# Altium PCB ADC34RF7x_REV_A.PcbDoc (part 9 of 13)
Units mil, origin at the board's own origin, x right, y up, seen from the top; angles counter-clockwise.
Board outline 6250 x 2716.54 mil, 18 copper layers (Top Layer, L2 GND, L3 PWR, L4 GND, L5 PWR/SIG, L6 GND, L7 SIGNAL, L8 GND, L9 GND, L10 SIGNAL, L11 GND, L12 SIGNAL, L13 GND, L14 PWR, L15 GND, L16 PWR/SIG, L16 GND, Bottom Layer), stack 95.314 mil thick; 668 components, 786 nets, 3150 pads, 2020 vias.
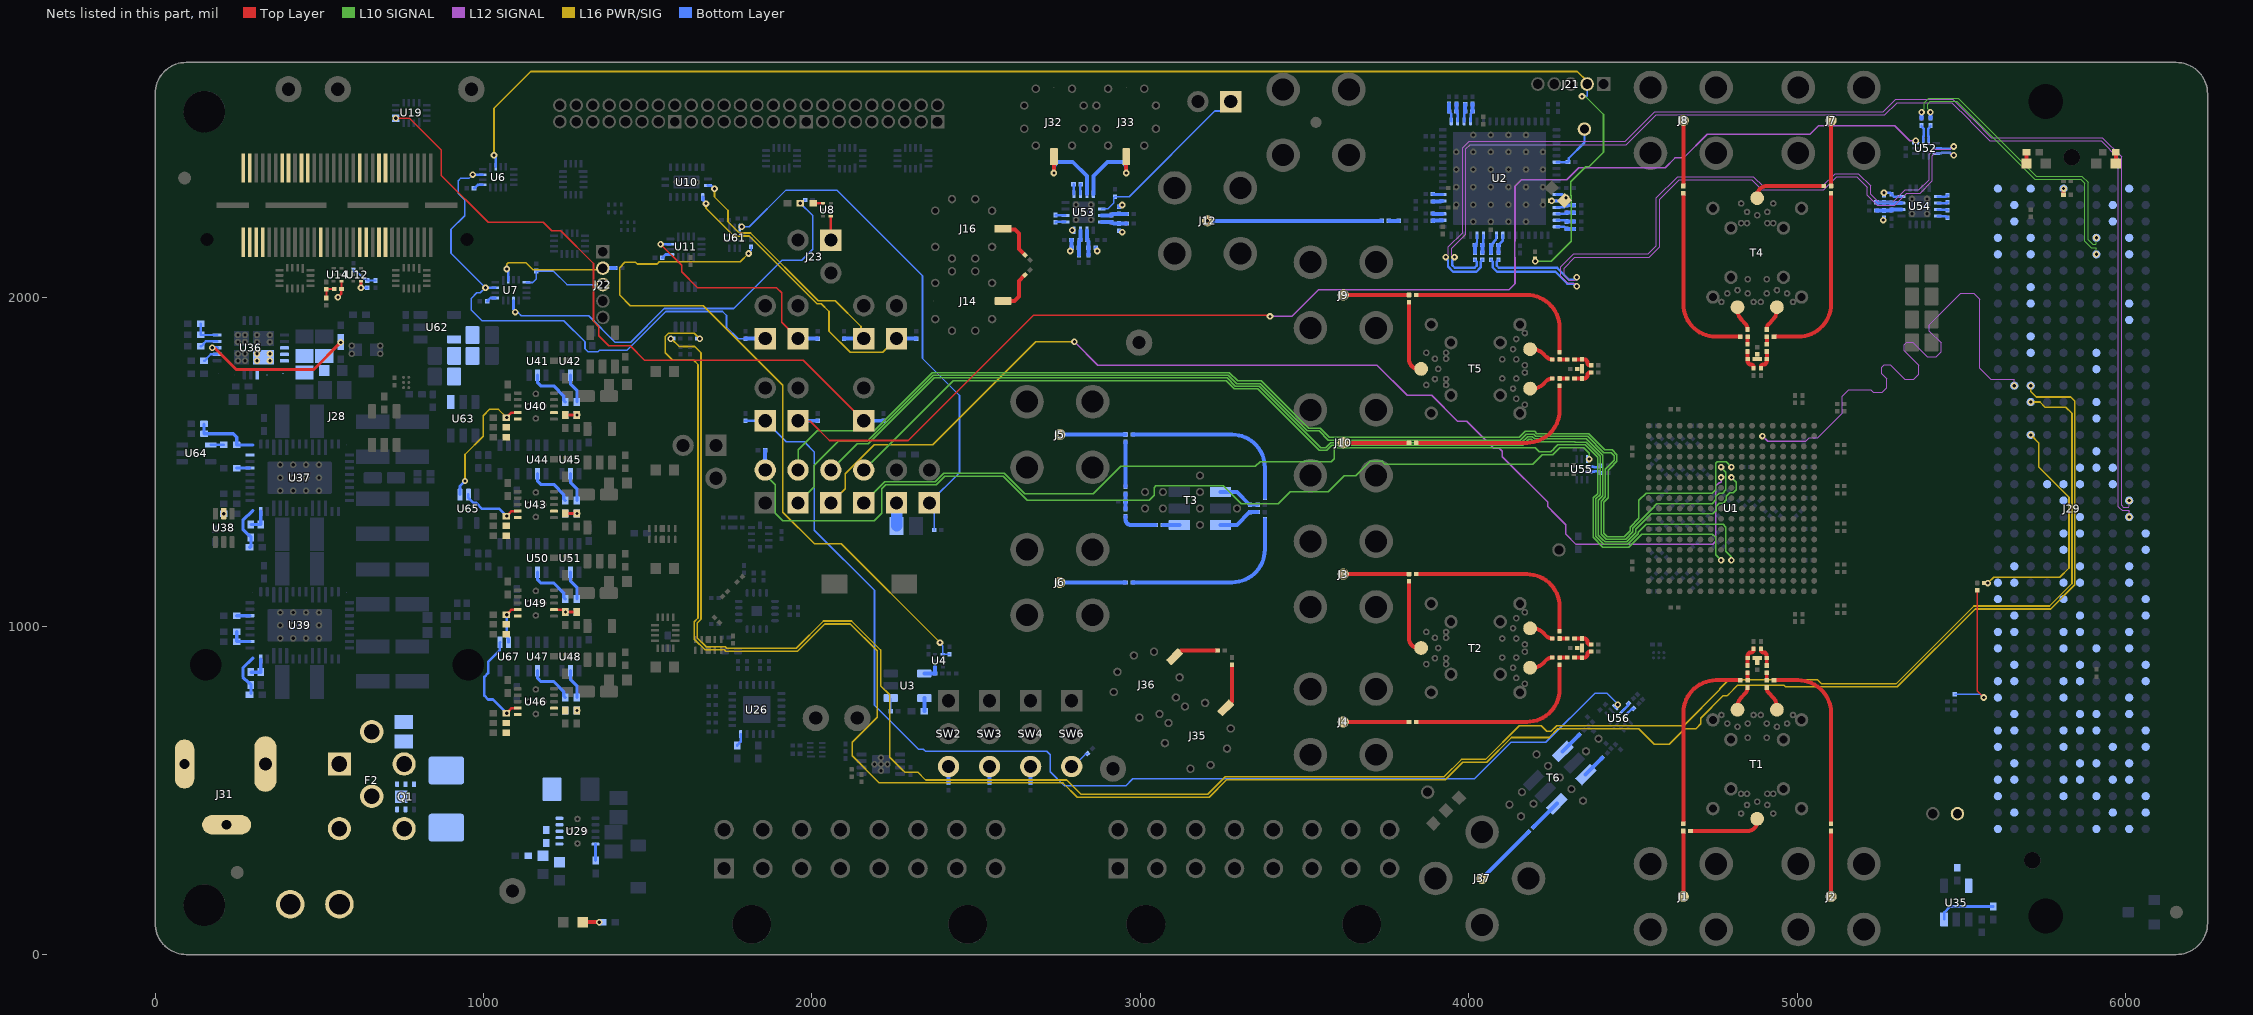
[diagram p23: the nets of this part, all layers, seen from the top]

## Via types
v1: diameter 20, hole 10, Top Layer to Bottom Layer, tented both sides, 1793 vias
v2: diameter 24, hole 12, Top Layer to Bottom Layer, tented both sides, 168 vias
v3: diameter 18, hole 8, Top Layer to Bottom Layer, tented both sides, 59 vias

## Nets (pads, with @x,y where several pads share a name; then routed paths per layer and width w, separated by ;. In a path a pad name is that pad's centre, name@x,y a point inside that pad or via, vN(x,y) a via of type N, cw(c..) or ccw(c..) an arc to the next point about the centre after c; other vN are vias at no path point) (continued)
LVDSB15_P: J29.J13 U1.F2 | length 1593.7
  L12 SIGNAL w3.5: 5025.69,1562.24 5037.18,1573.74 5063.44,1573.74 5122.33,1632.63 5137.41,1647.71 5137.41,1700.68 5156.58,1719.85 5223.68,1719.85 5231.29,1712.24 5258.63,1712.24 5272.65,1726.26 5272.65,1753.6 5257.04,1769.21 5257.04,1788.27 5265.21,1796.44 5284.27,1796.44 5328.44,1752.26 5355.78,1752.26 5369.8,1766.29 5369.8,1793.63 5325.63,1837.8 5325.63,1856.86 5333.8,1865.03 5352.85,1865.03 5397.03,1820.85 5424.37,1820.85 5438.39,1834.88 5438.39,1862.22 5402.22,1898.39 5402.22,1917.45 5497.93,2013.16 5537.24,2013.16 5555.61,1994.8 5555.61,1785.94 5572.01,1769.53 5589.27,1752.27 5659.37,1752.27 5661.42,1750.22 v1(5661.42,1732.27)
  L12 SIGNAL w4: v1(4894.49,1578.74) 4910.98,1562.24 5025.69,1562.24
MGTREFCLK0_FMC_N: C64.1 J29.D5 | length 876.9
  L10 SIGNAL w3.5: v1@5399.59,2564.64 v1(5406.04,2564.64) 5406.04,2566.3 5397.54,2574.8 5397.54,2589.76 5405.56,2597.78 5486.61,2597.78 5644.81,2439.58 5723.8,2360.59 5863.42,2360.59 5876,2348.02 5876,2338.55 5876.17,2338.38 5876.17,2226.16 5876,2225.99 5876,2188.55 5876.17,2188.38 5876.17,2171.96 5895.86,2152.27 5909.37,2152.27 5911.42,2150.22 v1(5911.42,2132.27)
  Bottom Layer w12.1: v1(5406.04,2564.64) 5406.04,2546.68 C64.1@5406.15,2546.56
MGTREFCLK0_FMC_P: C59.1 J29.D4 | length 893.7
  L10 SIGNAL w3.5: v1@5385.48,2564.64 v1(5379.03,2564.64) 5379.03,2566.3 5387.54,2574.8 5387.54,2593.9 5401.42,2607.78 5490.76,2607.78 5654.81,2443.73 5727.94,2370.59 5867.57,2370.59 5886,2352.16 5886,2342.69 5886.17,2342.52 5886.17,2222.02 5886,2221.85 5886,2192.69 5886.17,2192.52 5886.17,2176.1 5900,2162.27 5909.37,2162.27 5911.42,2164.32 v1(5911.42,2182.27)
  Bottom Layer w12.1: C59.1@5378.8,2546.45 5378.92,2546.56 5378.92,2564.52 v1(5379.03,2564.64)
MGTREFCLK0_LMK_N: R63.2 U52.4 | length 2044.3
  L12 SIGNAL w3.5: v1(4328.98,2035.16) 4328.98,2041.61 4326.93,2043.66 4301.69,2043.66 4280.33,2065.02 4280.33,2094.54 4319.56,2133.77 4546.13,2133.77 4571.14,2158.78 4571.14,2303.99 4636.27,2369.12 4866.61,2369.12 4896.62,2339.11 5077.11,2339.11 5115.93,2377.93 5186.41,2377.93 5223.58,2340.76 5223.58,2315.56 5247.62,2291.53 5293.42,2291.53 5330.09,2328.2 5370.61,2328.2 5402.2,2359.78 5402.2,2436.2 5418.02,2452.01 5466.47,2452.01 5474.97,2460.51 v1(5476.64,2460.51)
  Bottom Layer w7.4: R63.2@4068.18,2115.38 4068.18,2114.6 4073.3,2109.47 4073.3,2092.06 4086.29,2079.07 4263.96,2079.07 4300.57,2042.46 4318.35,2042.46 4325.65,2035.16 v1(4328.98,2035.16) ; U52.4@5424.03,2454.89 5424.27,2454.65 5438.81,2454.65 5440.25,2453.21 5466,2453.21 5473.3,2460.51 v1(5476.64,2460.51)
MGTREFCLK0_LMK_P: R62.2 U52.5 | length 1990.6
  L12 SIGNAL w3.5: v1(4328.98,2062.16) 4328.98,2055.71 4326.93,2053.66 4305.83,2053.66 4290.33,2069.16 4290.33,2090.4 4323.71,2123.77 4550.28,2123.77 4581.14,2154.64 4581.14,2299.85 4640.41,2359.12 4862.47,2359.12 4889.54,2332.04 4892.47,2329.11 5081.26,2329.11 5120.07,2367.93 5182.27,2367.93 5213.58,2336.62 5213.58,2311.42 5243.47,2281.53 5297.57,2281.53 5334.23,2318.2 5374.76,2318.2 5412.2,2355.64 5412.2,2432.05 5422.16,2442.01 5466.47,2442.01 5474.97,2433.51 v1(5476.64,2433.51)
  Bottom Layer w7.4: R62.2@4090.83,2115.38 4090.83,2114.6 4085.7,2109.47 4085.7,2097.2 4091.42,2091.47 4269.09,2091.47 4305.71,2054.86 4318.35,2054.86 4325.65,2062.16 v1(4328.98,2062.16) ; U52.5@5424.03,2439.14 5424.27,2439.38 5438.81,2439.38 5440.25,2440.81 5466,2440.81 5473.3,2433.51 v1(5476.64,2433.51)
MGTREFCLK1_FMC_N: C67.2 J29.B21 | length 3715.4
  L12 SIGNAL w3.5: v1(3956.79,2123.77) 3950.34,2123.77 3948.29,2125.82 3948.29,2150.43 3991.79,2193.93 3991.79,2452.89 4005.1,2466.2 4480.35,2466.2 4537.66,2523.52 4556.41,2542.27 4571.14,2557 5266.89,2557 5304.26,2594.36 5470.59,2594.36 5522.21,2542.75 5531.82,2533.14 5587.23,2477.73 5925.71,2477.73 5978,2425.43 5978,1363.9 5980.93,1360.97 5989.63,1352.27 6009.37,1352.27 6011.42,1350.22 v1(6011.42,1332.27)
  Bottom Layer w7.4: v1(3956.79,2123.77) 3956.79,2120.44 3949.49,2113.14 3949.49,2099.7 3957.71,2091.47 4018.21,2091.47 4023.93,2097.2 4023.93,2109.47 4018.81,2114.6 C67.2@4018.81,2115.38
MGTREFCLK1_FMC_P: C66.2 J29.B20 | length 3773.1
  L12 SIGNAL w3.5: v1(3929.79,2123.77) 3936.24,2123.77 3938.29,2125.82 3938.29,2154.57 3981.79,2198.07 3981.79,2457.03 4000.96,2476.2 4476.2,2476.2 4533.52,2533.52 4552.27,2552.27 4567,2567 5262.75,2567 5300.12,2604.36 5474.73,2604.36 5526.35,2552.75 5538.89,2540.21 5591.37,2487.73 5929.85,2487.73 5988,2429.57 5988,1368.04 5993.77,1362.27 6009.37,1362.27 6011.42,1364.32 v1(6011.42,1382.27)
  Bottom Layer w7.4: v1(3929.79,2123.77) 3929.79,2120.44 3937.09,2113.14 3937.09,2094.56 3952.57,2079.07 4023.35,2079.07 4036.33,2092.06 4036.33,2109.47 4041.46,2114.6 C66.2@4041.46,2115.38
NetC1_1: C1.1 C2.1 | length 567.7
  Top Layer w12.1: C2.1@4653.52,398.38 4653.52,735.2 cw(c4753.52,735.2) 4753.52,835.2 C1.1@4827.35,835.2
NetC1_2: C1.2 C3.2 R1.1 | length 23
  Top Layer w12.1: C1.2@4849.4,835.2 R1.1@4849.4,858.2
NetC2_2: C2.2 C4.1 J1.1 | length 200
  Top Layer w12.1: J1.1@4653.52,176.33 C2.2@4653.52,376.33
NetC3_1: C3.1 T1.2 | length 77.5
  Top Layer w12.1: T1.2@4818.52,745.38 4818.52,753 cw(c4862.74,753) 4831.47,784.27 4841.64,794.44 ccw(c4822.93,813.16) C3.1@4849.4,813.16
NetC4_2: C4.2 T1.1 | length 227.6
  Top Layer w12.1: C4.2@4675.57,376.33 4849.52,376.33 ccw(c4849.52,405.33) 4878.52,405.33 T1.1@4878.52,413.38
NetC5_2: C5.2 R3.1 R5.2
NetC6_1: C6.1 T1.3 | length 77.5
  Top Layer w12.1: C6.1@4907.64,813.16 ccw(c4934.11,813.16) 4915.4,794.44 4925.57,784.27 cw(c4894.3,753) 4938.52,753 T1.3@4938.52,745.38
NetC6_2: C6.2 C7.1 R6.1 | length 23
  Top Layer w12.1: C6.2@4907.64,835.2 R6.1@4907.64,858.2
NetC7_2: C7.2 C8.2 | length 567.7
  Top Layer w12.1: C7.2@4929.69,835.2 5003.52,835.2 cw(c5003.52,735.2) 5103.52,735.2 C8.2@5103.52,398.38
NetC8_1: C8.1 J2.1 | length 200
  Top Layer w12.1: J2.1@5103.52,176.33 C8.1@5103.52,376.33
NetC9_1: C9.1 C10.1 | length 567.7
  Top Layer w12.1: C10.1@3840.11,1158.29 4176.94,1158.29 cw(c4176.94,1058.29) 4276.94,1058.29 C9.1@4276.94,984.46
NetC9_2: C9.2 C11.2 R8.1 | length 23
  Top Layer w12.1: C9.2@4276.94,962.41 R8.1@4299.94,962.41
NetC10_2: C10.2 C12.1 J3.1 | length 200
  Top Layer w12.1: J3.1@3618.06,1158.29 C10.2@3818.06,1158.29
NetC11_1: C11.1 T2.2 | length 77.5
  Top Layer w12.1: T2.2@4187.11,993.29 4194.73,993.29 cw(c4194.73,949.07) 4226,980.34 4236.17,970.17 ccw(c4254.89,988.88) C11.1@4254.89,962.41
NetC12_2: C12.2 T2.1 | length 227.6
  Top Layer w12.1: C12.2@3818.06,1136.24 3818.06,962.29 ccw(c3847.06,962.29) 3847.06,933.29 T2.1@3855.11,933.29
NetC13_2: C13.2 R10.1 R12.2
NetC14_1: C14.1 T2.3 | length 77.5
  Top Layer w12.1: T2.3@4187.11,873.29 4194.73,873.29 ccw(c4194.73,917.51) 4226,886.24 4236.17,896.42 cw(c4254.89,877.7) C14.1@4254.89,904.17
NetC14_2: C14.2 C15.1 R13.1 | length 23
  Top Layer w12.1: C14.2@4276.94,904.17 R13.1@4299.94,904.17
NetC15_2: C15.2 C16.2 | length 567.7
  Top Layer w12.1: C16.2@3840.11,708.29 4176.94,708.29 ccw(c4176.94,808.29) 4276.94,808.29 C15.2@4276.94,882.12
NetC16_1: C16.1 J4.1 | length 200
  Top Layer w12.1: J4.1@3618.06,708.29 C16.1@3818.06,708.29
NetC17_1: C17.1 C18.1 | length 550.9
  Bottom Layer w12.1: C17.1@2977.05,1583.28 3279.28,1583.28 cw(c3279.28,1483.28) 3379.28,1483.28 C18.1@3379.28,1391.65
NetC17_2: C17.2 C20.1 J5.1 | length 200
  Bottom Layer w12.1: v1(2755,1583.28) C17.2@2955,1583.28
NetC19_1: C19.1 R17.1 T3.6 | length 129
  Bottom Layer w12.1: T3.6@3244.24,1408.28 3294.24,1408.28 3332.91,1369.6 C19.1@3357.24,1369.6
NetC20_2: C20.2 R15.1 | length 136.8
  Bottom Layer w12.1: R15.1@2955,1424.47 C20.2@2955,1561.23
NetC21_1: C21.1 R16.2 | length 111.2
  Bottom Layer w12.1: R16.2@2955,1334.38 2955,1324.38 ccw(c2971.1,1324.38) 2971.1,1308.28 C21.1@3046.99,1308.28
NetC21_2: C21.2 T3.3 | length 50
  Bottom Layer w12.1: C21.2@3069.04,1308.28 T3.3@3119.04,1308.28
NetC22_1: C22.1 R17.2 T3.4 | length 129
  Bottom Layer w12.1: T3.4@3244.24,1308.28 3294.24,1308.28 3332.91,1346.96 C22.1@3357.24,1346.96
NetC23_2: C23.2 C24.2 | length 550.9
  Bottom Layer w12.1: C24.2@2977.05,1133.28 3279.28,1133.28 ccw(c3279.28,1233.28) 3379.28,1233.28 C23.2@3379.28,1324.91
NetC24_1: C24.1 J6.1 | length 200
  Bottom Layer w12.1: v1(2755,1133.28) C24.1@2955,1133.28
NetC25_1: C25.1 C27.1 | length 567.7
  Top Layer w12.1: C25.1@4929.71,1881.33 5003.54,1881.33 ccw(c5003.54,1981.33) 5103.54,1981.33 C27.1@5103.54,2318.16
NetC25_2: C25.2 C26.2 R19.1 | length 23
  Top Layer w12.1: R19.1@4907.67,1858.33 C25.2@4907.67,1881.33
NetC26_1: C26.1 T4.2 | length 77.5
  Top Layer w12.1: C26.1@4907.67,1903.38 cw(c4934.14,1903.38) 4915.42,1922.1 4925.59,1932.27 ccw(c4894.32,1963.54) 4938.54,1963.54 T4.2@4938.54,1971.16
NetC27_2: C27.2 C28.1 J7.1 | length 200
  Top Layer w12.1: C27.2@5103.54,2340.21 J7.1@5103.54,2540.21
NetC28_2: C28.2 T4.1 | length 227.6
  Top Layer w12.1: T4.1@4878.54,2303.16 4878.54,2311.21 cw(c4907.54,2311.21) 4907.54,2340.21 C28.2@5081.5,2340.21
NetC29_2: C29.2 R21.1 R23.2
NetC30_1: C30.1 T4.3 | length 77.5
  Top Layer w12.1: T4.3@4818.54,1971.16 4818.54,1963.54 ccw(c4862.76,1963.54) 4831.5,1932.27 4841.67,1922.1 cw(c4822.95,1903.38) C30.1@4849.42,1903.38
NetC30_2: C30.2 C31.1 R24.1 | length 23
  Top Layer w12.1: R24.1@4849.42,1858.33 C30.2@4849.42,1881.33
NetC31_2: C31.2 C32.2 | length 567.7
  Top Layer w12.1: C32.2@4653.54,2318.16 4653.54,1981.33 ccw(c4753.54,1981.33) 4753.54,1881.33 C31.2@4827.38,1881.33
NetC32_1: C32.1 J8.1 | length 200
  Top Layer w12.1: C32.1@4653.54,2340.21 J8.1@4653.54,2540.21
NetC33_1: C33.1 C34.1 | length 567.7
  Top Layer w12.1: C34.1@3840.11,2008.27 4176.94,2008.27 cw(c4176.94,1908.27) 4276.94,1908.27 C33.1@4276.94,1834.44
NetC33_2: C33.2 C35.2 R26.1 | length 23
  Top Layer w12.1: C33.2@4276.94,1812.39 R26.1@4299.94,1812.39
NetC34_2: C34.2 C36.1 J9.1 | length 200
  Top Layer w12.1: J9.1@3618.06,2008.27 C34.2@3818.06,2008.27
NetC35_1: C35.1 T5.2 | length 77.5
  Top Layer w12.1: T5.2@4187.11,1843.27 4194.73,1843.27 cw(c4194.73,1799.05) 4226,1830.32 4236.17,1820.14 ccw(c4254.89,1838.86) C35.1@4254.89,1812.39
NetC36_2: C36.2 T5.1 | length 227.6
  Top Layer w12.1: C36.2@3818.06,1986.22 3818.06,1812.27 ccw(c3847.06,1812.27) 3847.06,1783.27 T5.1@3855.11,1783.27
NetC37_2: C37.2 R28.1 R30.2
NetC38_1: C38.1 T5.3 | length 77.5
  Top Layer w12.1: T5.3@4187.11,1723.27 4194.73,1723.27 ccw(c4194.73,1767.49) 4226,1736.22 4236.17,1746.39 cw(c4254.89,1727.68) C38.1@4254.89,1754.15
NetC38_2: C38.2 C39.1 R31.1 | length 23
  Top Layer w12.1: C38.2@4276.94,1754.15 R31.1@4299.94,1754.15
NetC39_2: C39.2 C40.2 | length 567.7
  Top Layer w12.1: C40.2@3840.11,1558.27 4176.94,1558.27 ccw(c4176.94,1658.27) 4276.94,1658.27 C39.2@4276.94,1732.1
NetC40_1: C40.1 J10.1 | length 200
  Top Layer w12.1: J10.1@3618.06,1558.27 C40.1@3818.06,1558.27
NetC53_1: C53.1 U2.37 | length 30.6
  Bottom Layer w12.1: C53.1@3890.96,2293.26 3914.83,2293.26 3916.33,2294.76 U2.37@3920.96,2294.76
NetC54_1: C54.1 U2.38 | length 30.6
  Bottom Layer w10: C54.1@3890.96,2315.95 3891.75,2315.95 3893.25,2314.45 U2.38@3920.96,2314.45
NetC56_1: C56.1 R33.2 | length 30
  Bottom Layer w12.1: C56.1@3756.86,2234.21 R33.2@3786.86,2234.21
NetC56_2: C56.2 J12.1 | length 530
  Bottom Layer w12.1: v1(3204.82,2234.21) C56.2@3734.82,2234.21
NetC57_2: C57.2 U2.35 | length 30.9
  Bottom Layer w12.1: C57.2@3890.96,2256.89 ccw(c3892.46,2256.89) 3892.46,2255.39 U2.35@3920.96,2255.39
NetC59_2: C59.2 U52.1 | length 51.8
  Bottom Layer w7.4: C59.2@5378.8,2524.4 5378.8,2521.06 5386.1,2513.76 5386.1,2492.52 5384.66,2491.09 U52.1@5384.66,2476.54 U52.1@5384.42,2476.31
NetC62_2: C62.2 R157.1 R158.1 R208.1 R209.1 U53.8 | length 72
  Bottom Layer w9: v1(2792.78,2205.32) U53.8@2797.78,2205.32 ; R158.1@2863.88,2152.32 2864.67,2152.32 2866.47,2150.52 2866.47,2149.73 2866.78,2149.42 2866.78,2144.42 v1(2868.88,2142.32)
  Bottom Layer w12: v1(2786.58,2142.37) 2786.58,2144.53 2790.29,2148.24 C62.2@2790.29,2175.32 ; R208.1@2935.43,2277.31 2935.43,2278.1 2935.73,2278.4 2939.35,2278.4 2943.27,2282.31 v1(2945.43,2282.31) ; R209.1@2939.51,2203.72 2943.21,2200.01 v1(2945.38,2200.01)
NetC63_2: C63.2 R159.1 R160.1 U54.8 | length 73.1
  Bottom Layer w8: v1@5264.71,2236.37 R160.1@5264.73,2243.46 ; R159.1@5264.73,2312.6 v1(5264.74,2319.69) 5283.09,2319.69 5284.64,2318.14 5285.43,2318.14 5287.73,2315.84 C63.2@5287.73,2315.05 5287.73,2314.26 5290.03,2311.97 5290.81,2311.97 5295.13,2307.65 U54.8@5317.73,2307.65
  other v1: 5262.71,2236.37
NetC64_2: C64.2 U52.2 | length 51.8
  Bottom Layer w7.4: U52.2@5400.53,2476.42 5400.29,2476.66 5400.29,2491.21 5398.85,2492.64 5398.85,2513.88 5406.15,2521.18 C64.2@5406.15,2524.52
NetC65_2: C65.2 U56.1 | length 32.3
  Bottom Layer w7.4: U56.1@4467.01,740.38 4486.14,759.51 4486.14,764.01 C65.2@4486.7,764.57
NetC66_1: C66.1 R37.1 U2.27 | length 55
  Bottom Layer w7.4: R37.1@4041.46,2160.18 4041.69,2160.18 4044.54,2163.03 4044.54,2166.93 4044.97,2167.37 U2.27@4044.97,2190.43
  Bottom Layer w12.1: R37.1@4041.16,2160.43 R37.1@4041.16,2160.43 4041.46,2160.18 C66.1@4041.46,2137.43
NetC67_1: C67.1 R37.2 U2.28 | length 56.6
  Bottom Layer w7.4: R37.2@4018.81,2160.18 4019.65,2160.18 4022.49,2163.03 4022.49,2164.57 4025.29,2167.37 U2.28@4025.29,2190.43
  Bottom Layer w12.1: C67.1@4018.81,2137.43 4018.81,2160.18 R37.2@4019.11,2160.43 R37.2@4019.11,2160.43
NetC68_2: C68.2 U56.2 | length 32.3
  Bottom Layer w7.4: U56.2@4478.15,729.24 4497.33,748.42 4501.73,748.42 C68.2@4502.29,748.98
NetC69_2: C69.2 U3.5 | length 40
  Bottom Layer w12: C69.2@2342.36,740.77 U3.5@2342.36,780.77
NetC70_1: C70.1 U2.34 | length 30.9
  Bottom Layer w12.1: C70.1@3890.96,2234.21 cw(c3892.46,2234.21) 3892.46,2235.71 U2.34@3920.96,2235.71
NetC71_1: C71.1 D4.2 F1.2 F2.2 Q1.3 R108.2 U29.3 U29.4 U29.5
NetC71_2: C71.2 D4.1 F2.4 Q1.1 Q1.2 Q1.5 Q1.6 Q1.8
NetC72_1: C72.1 U2.11 | length 40.3
  Bottom Layer w8: U2.11@4274.49,2314.45 U2.11@4267.42,2314.45 4281.49,2314.44 4285.82,2314.44 4295.82,2304.43 v1(4296.5,2304.43)
NetC73_1: C73.1 U2.12 | length 26
  Top Layer w8: C73.1@4248.78,2295.44 4249.44,2294.78 v1(4253.33,2294.78)
  Bottom Layer w8: v1(4253.33,2294.78) U2.12@4267.42,2294.76 ; U2.12@4260.34,2294.76 U2.12@4267.42,2294.76
NetC74_2: C74.2 PP1.1 U35.5
NetC75_2: C75.2 T6.6 | length 70.7
  Bottom Layer w12: T6.6@4286.29,618.57 C75.2@4336.29,668.57
NetC97_2: C97.2 R108.1 R111.2 U29.2
NetC98_2: C98.2 U29.1
NetC99_2: C99.2 T6.4 | length 70.7
  Bottom Layer w12: T6.4@4356.34,548.51 C99.2@4406.34,598.51
NetC100_1: C100.1 R188.1 R208.2 U53.3 | length 77.9
  Bottom Layer w12.1: U53.3@2882.43,2250.59 2911.25,2250.59 R188.1@2912.43,2251.77 2915.93,2255.27 R208.2@2935.43,2255.27 C100.1@2958.43,2255.27
NetC101_1: C101.1 R188.2 R209.2 U53.4 | length 77.7
  Bottom Layer w12.1: U53.4@2882.43,2230.9 2911.25,2230.9 2911.39,2230.76 2912.18,2230.76 2912.43,2230.51 R188.2@2912.43,2229.72 2919.77,2226.22 R209.2@2935.43,2226.22 C101.1@2958.43,2226.22
NetC108_1: C108.1 R132.2 R134.2 R136.2 U40.7 | length 35
  Top Layer w10: C108.1@1249.61,1643.03 v1(1284.61,1643.03)
NetC109_1: C109.1 R138.2 R140.2 R142.2 U43.7 | length 35
  Top Layer w10: C109.1@1249.61,1343.03 v1(1284.61,1343.03)
NetC122_1: C122.1 R144.1 R146.2 R148.2 U46.7
  other v1: 1284.61,743.03
NetC124_1: C124.1 R150.1 R152.2 R154.2 U49.7 | length 73.7
  Top Layer w8: U49.7@1214.61,1050.12 1243.76,1050.12 1249.61,1044.28 v1(1249.61,1043.03)
  Top Layer w10: v1(1249.61,1043.03) R152.2@1284.61,1043.03
NetC130_1: C130.1 C131.1 C167.1 FB1.1 U36.10 U36.11 U36.12 U36.13 U36.14 U36.15 U36.27
NetC184_2: C184.2 C187.2 C188.2 C189.2 U62.5 U63.1
NetC205_2: C205.2 U36.21 | length 49.4
  Bottom Layer w7: C205.2@149.09,1807.64 151.06,1807.64 157.4,1813.98 157.4,1815.95 169.09,1827.64 U36.21@189.09,1827.64
NetC218_2: C218.2 U37.44 | length 40
  Bottom Layer w9: C218.2@248.38,1481.3 U37.44@288.38,1481.3
NetC227_2: C227.2 U39.44 | length 40
  Bottom Layer w10: C227.2@248.38,1031.81 U39.44@288.38,1031.81
NetC259_1: C259.1 R158.2 R175.2 U53.6 | length 77.9
  Bottom Layer w12.1: U53.6@2837.16,2205.32 2837.16,2176.49 R175.2@2838.34,2175.32 2841.84,2171.82 R158.2@2841.84,2152.32 C259.1@2841.84,2129.32
NetC260_1: C260.1 R157.2 R175.1 U53.7 | length 77.7
  Bottom Layer w12.1: C260.1@2812.79,2129.32 R157.2@2812.79,2152.32 2812.79,2167.98 R175.1@2816.29,2175.32 2817.08,2175.32 2817.33,2175.57 2817.33,2176.35 2817.47,2176.49 U53.7@2817.47,2205.32
NetC261_1: C261.1 R160.2 R176.2 U54.6 | length 78
  Bottom Layer w12.1: C261.1@5241.73,2265.68 5281.4,2265.68 5281.86,2266.15 5287.48,2266.15 5287.73,2266.4 R176.2@5287.73,2267 5287.73,2267.97 5287.98,2268.22 5288.76,2268.22 5288.82,2268.27 U54.6@5317.73,2268.27
NetC262_1: C262.1 R159.2 R176.1 U54.7 | length 78
  Bottom Layer w12.1: C262.1@5241.73,2290.55 R159.2@5264.73,2290.55 5281.4,2290.55 5281.86,2290.09 5287.48,2290.09 5287.73,2289.84 R176.1@5287.73,2289.05 5287.73,2288.26 5287.98,2288.02 5288.76,2288.02 5288.82,2287.96 U54.7@5317.73,2287.96
NetC265_1: C265.1 T6.3 | length 100
  Bottom Layer w12.1: C265.1@4197.76,388.62 T6.3@4268.47,459.33
NetC265_2: C265.2 J37.1 | length 200
  Bottom Layer w12.1: v1(4040.75,231.61) C265.2@4182.17,373.03
NetD1_2: D1.2 R83.2 | length 35
  Top Layer w12: D1.2@5970.47,2408.52 R83.2@5970.47,2443.52
NetD2_2: D2.2 R87.2 | length 35
  Top Layer w12: D2.2@5698.36,2408.51 R87.2@5698.36,2443.51
NetD3_2: D3.2 R110.2 | length 50
  Top Layer w12: D3.2@1302.21,98.59 v1(1352.21,98.59)
NetF2_1: F2.1 J31.1 TP11.1
NetF2_3: F2.3 J31.2 J31.3 TP12.1
NetJ14_1: J14.1 R43.2 | length 127.2
  Top Layer w12.1: J14.1@2581.34,1989.11 J14.1@2582.11,1989.88 2582.88,1990.65 2617.49,1990.65 2630.09,2003.25 2630.09,2050.81 R43.2@2647.8,2068.52
NetJ15_1: J15.1 U1.K14 | length 3134.5
  L10 SIGNAL w4: J15.1@2157.76,1375.36 2221.38,1438.99 2374.87,1438.99 2401.38,1465.49 2586.06,1465.49 2648.86,1402.69 2856.38,1402.69 2941.18,1487.5 3350.8,1487.5 3364.56,1501.26 3499.58,1501.26 3500.06,1501.73 3540.51,1501.73 3541.4,1500.84 3581.85,1500.84 3590.63,1509.63 3590.63,1539.19 3593.83,1542.39 4203.21,1542.39 4215.32,1530.29 4250.53,1530.29 4259.32,1539.07 4259.32,1539.91 4271.15,1551.74 4354.17,1551.74 4392.31,1513.6 4392.31,1403.83 4379.07,1390.6 4379.07,1270.01 4408.31,1240.78 4487.51,1240.78 4524,1277.27 4524,1277.44 4526.34,1279.78 4742.22,1279.78 4752.01,1269.99 4752.01,1217.26 v1(4768.5,1200.76)
NetJ15_2: J15.2 U1.J14 | length 3274.4
  L10 SIGNAL w4: J15.2@2157.76,1475.36 2430.12,1747.73 3261.33,1747.73 3286.55,1722.52 3357.91,1722.52 3545.46,1534.96 3567.28,1534.96 3582.71,1550.39 4164.11,1550.39 4182.2,1568.49 4191.09,1568.49 4197.66,1561.92 4322.82,1561.92 4324.99,1559.74 4357.48,1559.74 4400.31,1516.92 4400.31,1400.52 4387.07,1387.28 4387.07,1273.5 4400.31,1260.27 4400.31,1260.09 4403.62,1256.78 4403.79,1256.78 4406.62,1253.96 4406.62,1253.78 4411.62,1248.78 4484.19,1248.78 4516,1280.59 4516,1286.07 4540.2,1310.28 4774.72,1310.28 4783.5,1301.49 4783.5,1227.57 4800,1211.07 v1(4800,1200.76)
NetJ16_1: J16.1 R44.2 | length 127.2
  Top Layer w12.1: J16.1@2582.11,2209.88 2583.65,2208.34 2618.26,2208.34 2630.86,2195.74 2630.86,2148.18 R44.2@2648.57,2130.47
NetJ17_1: J17.1 U1.K6 | length 3421.9
  L16 PWR/SIG w4: J17.1@2057.76,1375.36 2101.18,1418.79 2101.18,1463.86 2189.23,1551.91 2368.12,1551.91 2681.82,1865.61 v1(2799.42,1865.61)
  L12 SIGNAL w4: 4528.51,1248.78 4743.22,1248.78 4752.76,1258.31 4752.76,1426.72 4762.29,1436.26 4766.16,1436.26 4768.5,1438.6 v1(4768.5,1452.76)
  L12 SIGNAL w5: v1(2799.42,1865.61) 2870.76,1794.27 3720.9,1794.27 3812.48,1702.69 3887.18,1702.69 3966.06,1623.81 3994.18,1623.81 4076.26,1541.73 4093.04,1541.73 4102.12,1532.65 4102.12,1515.86 4240.28,1377.71 4240.28,1364.34 4263.72,1340.9 4263.72,1340.58 4295.16,1309.14 4295.16,1280.3 4326.68,1248.78 4528.51,1248.78
NetJ17_2: J17.2 U1.J6 | length 3398.2
  L10 SIGNAL w4: J17.2@2057.76,1475.36 2137.35,1554.95 2172.07,1554.95 2372.85,1755.73 3264.65,1755.73 3289.86,1730.52 3361.72,1730.52 3548.97,1543.27 3554.32,1543.27 3554.63,1542.96 3563.97,1542.96 3579.4,1558.39 4160.79,1558.39 4179.19,1576.78 4194.11,1576.78 4200.97,1569.92 4358.62,1569.92 4408.31,1520.23 4408.31,1397.2 4395.07,1383.97 4395.07,1276.81 4408.31,1263.58 4415.11,1256.78 4480.88,1256.78 4508,1283.9 4508,1295 4555.77,1342.77 4742.73,1342.77 4753.41,1353.46 4753.41,1364.39 4763.6,1374.58 4774.53,1374.58 4784.63,1384.67 4784.63,1395.6 4794.53,1405.51 4805.47,1405.51 4815,1415.05 4815,1437.76 v1(4800,1452.76)
NetJ18_1: J18.1 U1.K5 | length 3595.1
  L10 SIGNAL w4: J18.1@1957.76,1375.36 2006.83,1424.44 2006.83,1489.43 2080.35,1562.95 2168.76,1562.95 2369.54,1763.73 3267.96,1763.73 3293.17,1738.52 3365.03,1738.52 3508.92,1594.63 3544.17,1594.63 3572.4,1566.39 4157.31,1566.39 4175.7,1584.78 4197.42,1584.78 4204.29,1577.92 4361.93,1577.92 4411.4,1528.45 4434,1528.45 4443.37,1519.08 4443.37,1505.83 4433.78,1496.23 4433.78,1495.34 4416.43,1477.99 4416.43,1394.01 4403.07,1380.66 4403.07,1280.13 4418.42,1264.78 4477.57,1264.78 4500,1287.21 4500,1298.32 4564.53,1362.84 4564.53,1364.48 4573.31,1373.27 4741.73,1373.27 4752.76,1384.3 4752.76,1395.23 4762.29,1404.76 4773.22,1404.76 4783.5,1415.05 4783.5,1458.97 4783.46,1459.01 4783.46,1469.29 v1(4768.5,1484.25)
NetJ18_2: J18.2 U1.J5 | length 3605.9
  L10 SIGNAL w4: J18.2@1957.76,1475.36 1957.76,1536.42 2016.7,1595.36 2189.86,1595.36 2366.22,1771.73 3271.28,1771.73 3296.49,1746.52 3368.34,1746.52 3500.06,1614.8 3501.27,1614.8 3513.45,1602.63 3547.48,1602.63 3575.72,1574.39 4153.99,1574.39 4172.39,1592.78 4200.73,1592.78 4207.6,1585.92 4365.24,1585.92 4414.71,1536.45 4437.32,1536.45 4451.37,1522.39 4451.37,1502.51 4441.78,1492.92 4441.78,1492.03 4424.43,1474.68 4424.43,1390.7 4411.07,1377.34 4411.07,1283.44 4421.73,1272.78 4474.25,1272.78 4492,1290.53 4492,1301.63 4518.46,1328.09 4518.46,1383.02 4540.2,1404.76 4741.73,1404.76 4752.5,1415.54 4752.5,1495.34 4757.41,1500.25 4784,1500.25 v1(4800,1484.25)
NetJ19_1: J19.1 R51.1 | length 70
  Bottom Layer w35: R51.1@2257.76,1305.36 J19.1@2257.76,1375.36
NetJ21_2: J21.2 R53.2 U6.2 | length 4294
  Top Layer w8: R53.2@4202.45,2111.31 R53.2@4202.45,2118.38
  L16 PWR/SIG w5: v1(1031.86,2433.62) 1031.86,2576.86 1144.04,2689.04 4330.96,2689.04 4360.66,2659.34 J21.2@4360.66,2650.7
  L10 SIGNAL w5: v1(4202.44,2111.3) 4251.7,2111.3 4312,2171.59 4312,2310.85 4311.05,2311.81 4311.05,2353.05 4356.66,2398.66 4366.32,2398.66 4410.66,2443 4410.66,2557.88 4355.54,2613 v1(4345.07,2613)
  Bottom Layer w5: v1(4345.07,2613) 4361.07,2613 4361.07,2650.28 J21.2@4360.66,2650.7
  Bottom Layer w8: v1(1031.86,2433.62) 1031.86,2430.37 1036.86,2425.37 U6.2@1036.86,2398.62
NetJ22_2: J22.2 R59.1 U7.2 | length 393.4
  L16 PWR/SIG w5: v1(1070.49,2087.4) 1071.02,2087.94 1071.02,2101.62 1075.44,2106.04 1129.66,2106.04 1150.73,2084.97 1358.5,2084.97 J22.2@1363.54,2090.01
  Bottom Layer w8: v1(1070.49,2087.4) 1070.49,2084.15 1075.49,2079.15 U7.2@1075.49,2054.37 U7.2@1075.49,2052.4
  Bottom Layer w12: J22.2@1363.54,2090.01 R59.1@1400.32,2090.01
NetJ22_3: J22.3 R187.1 U7.5 | length 279.3
  Bottom Layer w5: U7.5@1130.6,2046.5 1149.91,2046.5 1156.02,2052.6 1156.02,2052.7 1159.82,2056.5 1160.6,2056.5 R187.1@1160.6,2081.5 1212.77,2081.5 1254.25,2040.01 J22.3@1363.54,2040.01
NetJ23_1: J23.1 U8.1 | length 73
  Top Layer w8: J23.1@2057.76,2175.36 U8.1@2057.76,2248.38
NetJ24_1: J24.1 R73.1 U6.15 U7.15 | length 1664.5
  Bottom Layer w5: v1(967.49,2375) 955.78,2363.28 929.87,2363.28 923,2356.41 923,2317.7 942.45,2298.25 942.45,2250.01 901,2208.57 901,2135.86 v1(1006.12,2030.75) 990.37,2015 979.82,2015 962.71,1997.89 962.71,1962.52 995.48,1929.75 1244.67,1929.75 1308.85,1865.57 1308.85,1844.65 1317.97,1835.53 1348.36,1835.53 1353.33,1840.5 1436.81,1840.5 1554.56,1958.25 1727.62,1958.25 1740.12,1945.74 1740.12,1910.94 1775.7,1875.36 R73.1@1797.76,1875.36
  Bottom Layer w8: v1(967.49,2375) U6.15@997.49,2375 ; v1(1006.12,2030.75) U7.15@1036.12,2030.75
  Bottom Layer w12: R73.1@1797.76,1875.36 J24.1@1857.76,1875.36
NetJ25_1: J25.1 R74.1 U11.15 | length 691.9
  Top Layer w5: v1(1539.13,2163.03) 1603.5,2098.66 1603.5,2078.64 1651.27,2030.88 1891.76,2030.88 1907.71,2014.92 1907.71,1925.41 J25.1@1957.76,1875.36
  Bottom Layer w8: v1(1539.13,2163.03) U11.15@1569.13,2163.03
  Bottom Layer w12: J25.1@1957.76,1875.36 R74.1@2017.76,1875.36
NetJ26_1: J26.1 R72.1 U10.9 | length 779.5
  L16 PWR/SIG w5: v1(1703.31,2332.09) 1703.31,2306.94 1744.46,2265.79 1744.46,2231.36 1778.79,2197.03 1813.21,2197.03 2019.38,1990.86 2070.95,1990.86 2149.4,1912.41 2149.4,1883.72 J26.1@2157.76,1875.36
  Bottom Layer w8: U10.9@1683.31,2342.09 1684.03,2341.36 1692.62,2341.36 1701.9,2332.09 v1(1703.31,2332.09)
  Bottom Layer w12: R72.1@2097.76,1875.36 J26.1@2157.76,1875.36
NetJ27_1: J27.1 R71.1 U10.10 | length 913.1
  L16 PWR/SIG w5: v1(1677.56,2286.65) 1677.56,2272.19 1761.72,2188.03 1809.49,2188.03 2015.65,1981.86 2028.38,1981.86 2052.14,1958.11 2052.14,1897.88 2116.46,1833.56 2215.95,1833.56 J27.1@2257.76,1875.36
  Bottom Layer w8: U10.10@1667.56,2306.65 1668.28,2305.93 1668.28,2297.34 1677.56,2288.06 v1(1677.56,2286.65)
  Bottom Layer w12: J27.1@2257.76,1875.36 R71.1@2317.76,1875.36
NetJ28_15: J28.15
NetJ28_16: J28.16
NetJ28_17: J28.17
NetJ28_18: J28.18
NetJ28_22: J28.22
NetJ28_23: J28.23
NetJ28_24: J28.24
NetJ28_36: J28.36
NetJ28_39: J28.39
NetJ28_41: J28.41
NetJ28_45: J28.45
NetJ28_47: J28.47
NetJ28_54: J28.54
NetJ28_56: J28.56
NetJ28_57: J28.57
NetJ28_58: J28.58
NetJ28_59: J28.59
NetJ28_60: J28.60
NetJ29_A22: J29.A22
NetJ29_A23: J29.A23
NetJ29_A26: J29.A26
NetJ29_A27: J29.A27
NetJ29_A30: J29.A30
NetJ29_A31: J29.A31
NetJ29_A34: J29.A34
NetJ29_A35: J29.A35
NetJ29_A38: J29.A38
NetJ29_A39: J29.A39
NetJ29_B1: J29.B1
NetJ29_B4: J29.B4
NetJ29_B5: J29.B5
NetJ29_B8: J29.B8
NetJ29_B9: J29.B9
NetJ29_B24: J29.B24
NetJ29_B25: J29.B25
NetJ29_B28: J29.B28
NetJ29_B29: J29.B29
NetJ29_B32: J29.B32
NetJ29_B33: J29.B33
NetJ29_B36: J29.B36
NetJ29_B37: J29.B37
NetJ29_B40: J29.B40
NetJ29_C2: J29.C2
NetJ29_C3: J29.C3
NetJ29_C18: J29.C18
NetJ29_C19: J29.C19
NetJ29_C35: J29.C35
NetJ29_C37: J29.C37
NetJ29_C39: J29.C39
NetJ29_D11: J29.D11
NetJ29_D12: J29.D12
NetJ29_D14: J29.D14
NetJ29_D15: J29.D15
NetJ29_D17: J29.D17
NetJ29_D18: J29.D18
NetJ29_D29: J29.D29
NetJ29_D33: J29.D33
NetJ29_D34: J29.D34
NetJ29_D36: J29.D36
NetJ29_D38: J29.D38
NetJ29_D40: J29.D40
NetJ29_E18: J29.E18
NetJ29_E19: J29.E19
NetJ29_E21: J29.E21
NetJ29_E22: J29.E22
NetJ29_E24: J29.E24
NetJ29_E25: J29.E25
NetJ29_E27: J29.E27
NetJ29_E28: J29.E28
NetJ29_E30: J29.E30
NetJ29_E31: J29.E31
NetJ29_E33: J29.E33
NetJ29_E34: J29.E34
NetJ29_E36: J29.E36
NetJ29_E37: J29.E37
NetJ29_F1: J29.F1 R85.2 | length 18.7
  Top Layer w12: R85.2@5811.42,2313.53 v1(5811.42,2332.27)
NetJ29_F19: J29.F19
NetJ29_F20: J29.F20
NetJ29_F22: J29.F22
NetJ29_F23: J29.F23
NetJ29_F25: J29.F25
NetJ29_F26: J29.F26
NetJ29_F28: J29.F28
NetJ29_F29: J29.F29
NetJ29_F31: J29.F31
NetJ29_F32: J29.F32
NetJ29_F34: J29.F34
NetJ29_F35: J29.F35
NetJ29_F37: J29.F37
NetJ29_F38: J29.F38
NetJ29_G19: J29.G19
NetJ29_H1: J29.H1
NetJ29_H4: J29.H4
NetJ29_H5: J29.H5
NetJ29_H7: J29.H7
NetJ29_H8: J29.H8
NetJ29_H10: J29.H10
NetJ29_H11: J29.H11
NetJ29_H13: J29.H13 R217.2 | length 6939.4
  L16 PWR/SIG w5: v1(1658.32,1875.36) 1641.82,1891.86 1563.53,1891.86 1553.86,1882.2 1553.86,1868.53 1553.86,1832.39 1576.4,1809.86 1639.88,1809.86 1653.31,1796.44 1653.31,1024.43 1641.88,1013.01 1641.88,960.15 1674.21,927.82 1732.75,927.82 1737.18,923.39 1956.13,923.39 2039.21,1006.47 2117.14,1006.47 2198.74,924.87 2198.74,722.1 2122.7,646.05 2122.7,604.92 2205.08,522.54 2764.76,522.54 2808.3,479 3209.52,479 3262.56,532.04 3928.66,532.04 3981.73,585.11 4054.85,585.11 4130.5,660.75 4244.41,660.75 4271.47,687.81 4517.58,687.81 4564.72,640.67 4610.48,640.67 4657.63,687.81 4691.98,687.81 4706.61,702.44 4706.61,719.83 4774.44,787.67 4786.8,787.67 4791.06,791.94 4818.62,819.5 4960.29,819.5 4964.78,815 5305,815 5542.23,1052.23 5772.23,1052.23 5845.92,1125.92 5845.92,1685.49 5833.64,1697.77 5728.24,1697.77 5711.42,1714.59 v1(5711.42,1732.27)
  Bottom Layer w5: R217.2@1651.23,1875.36 v1(1658.32,1875.36)
NetJ29_H14: J29.H14 R218.2 | length 6567
  L16 PWR/SIG w5: v1(1570.36,1875.36) 1571.79,1875.36 1595.76,1851.4 1643.37,1851.4 1650.95,1843.82 1662.31,1832.46 1662.31,1128.52 1662.31,1075.36 1662.31,1020.71 1650.88,1009.28 1650.88,963.88 1677.94,936.82 1736.48,936.82 1740.91,932.39 1952.4,932.39 2035.48,1015.47 2120.87,1015.47 2209.18,927.16 2209.18,818.57 2237.07,790.67 2237.07,600.88 2276.96,561 2277.08,561 2283.49,554.59 2323.12,554.59 2346.17,531.54 2775.62,531.54 2819.16,488 3205.8,488 3258.83,541.04 3924.94,541.04 3978.01,594.11 4051.12,594.11 4153.83,696.81 4220.9,696.81 4237.9,679.81 4250.74,679.81 4267.74,696.81 4654.82,696.81 4764.87,806.86 4764.87,809.59 4791.9,836.62 5062.01,836.62 5074.63,824 5301.27,824 5538.5,1061.23 5768.5,1061.23 5836.92,1129.65 5836.92,1648.21 5818.36,1666.77 5755,1666.77 5739.5,1682.27 v1(5711.42,1682.27)
  Bottom Layer w5: v1(1570.36,1875.36) R218.2@1577.45,1875.36
NetJ29_H16: J29.H16 R200.2 | length 825
  Top Layer w5: R200.2@5570.76,1131.13 v1(5580.76,1131.13)
  L16 PWR/SIG w5: v1(5580.76,1131.13) 5598.62,1149 ; 5693.84,1149 5598.62,1149 ; v1(5711.42,1582.27) 5735.92,1557.77 5735.92,1484.43 5827.92,1392.43 5827.92,1176.85 5800.07,1149 5598.62,1149
NetJ29_J2: J29.J2
NetJ29_J3: J29.J3
NetJ29_J24: J29.J24
NetJ29_J25: J29.J25
NetJ29_J27: J29.J27
NetJ29_J28: J29.J28
NetJ29_J30: J29.J30
NetJ29_J31: J29.J31
NetJ29_J33: J29.J33
NetJ29_J34: J29.J34
NetJ29_J36: J29.J36
NetJ29_J37: J29.J37
NetJ29_J39: J29.J39
NetJ29_K1: J29.K1
NetJ29_K4: J29.K4
NetJ29_K5: J29.K5
NetJ29_K25: J29.K25
NetJ29_K26: J29.K26
NetJ29_K28: J29.K28
NetJ29_K29: J29.K29
NetJ29_K31: J29.K31
NetJ29_K32: J29.K32
NetJ29_K34: J29.K34
NetJ29_K35: J29.K35
NetJ29_K37: J29.K37
NetJ29_K38: J29.K38
NetJ29_K40: J29.K40
NetJ30_1: J30.1 R88.1 U19.5 U19.6 | length 2047.2
  Top Layer w5: v1(733.03,2546.81) 774.61,2546.81 871.42,2450 871.42,2372.09 1014.09,2229.41 1182.13,2229.41 1207.76,2203.78 1235.24,2203.78 1334.9,2104.12 1334.9,1928.07 1351.23,1911.74 1351.23,1883.91 1381.49,1853.65 1446.43,1853.65 1490.31,1809.77 1973.35,1809.77 J30.1@2157.76,1625.36
  Bottom Layer w5: U19.5@733.03,2538.94 v1(733.03,2546.81) U19.6@733.03,2554.69
  Bottom Layer w12: J30.1@2157.76,1625.36 R88.1@2217.76,1625.36
NetJ32_1: J32.1 U53.15 | length 249.6
  Top Layer w12.1: v1(2737,2379.71) J32.1@2737,2429.71
  Bottom Layer w12.1: v1(2737,2379.71) 2737,2401.68 2748.66,2413.34 2794.26,2413.34 2837.16,2370.43 U53.15@2837.16,2315.55
NetJ33_1: J33.1 U53.16 | length 249.6
  Top Layer w12.1: v1(2957,2379.71) J33.1@2957,2429.71
  Bottom Layer w12.1: U53.16@2856.85,2315.55 2856.85,2370.43 2899.75,2413.34 2945.35,2413.34 2957,2401.68 v1(2957,2379.71)
NetJ34_1: J34.1 R162.1 U52.10 | length 4095.8
  Top Layer w5: J34.1@1957.76,1625.36 1959.36,1623.76 1994.81,1623.76 2053.41,1565.16 2293.11,1565.16 2674.79,1946.84 3384.45,1946.84 3385.32,1945.97 3392.01,1945.97 v1(3394.88,1943.1)
  Top Layer w8: v1@5361.04,2470.64 v1@5361.04,2477.71
  L12 SIGNAL w5: v1(3394.88,1943.1) 3461.4,1943.1 3542.07,2023.77 4122.17,2023.77 4141.02,2042.62 4141.02,2122.46 4140.57,2122.91 4140.57,2171.94 4141.02,2172.39 4141.02,2339.23 4160.9,2359.12 4298.27,2359.12 4335.39,2396.24 4598.85,2396.24 4628.36,2425.76 4654.37,2425.76 4726.39,2497.78 5039.2,2497.78 5064.94,2523.52 5297.55,2523.52 5343.34,2477.73 v1(5361.05,2477.73)
  Bottom Layer w5: v1@5360.87,2477.93 v1(5361.05,2477.73) ; U52.10@5361.04,2470.64 v1@5361.04,2477.71
  Bottom Layer w12: J34.1@1957.76,1625.36 R162.1@2017.76,1625.36
NetJ35_1: J35.1 R164.2 | length 139.6
  Top Layer w12.1: J35.1@3259.91,750.94 3279.35,770.39 3279.35,877.22 3279.28,877.29 3279.28,882.12 R164.2@3279.03,882.37
NetJ36_1: J36.1 R177.2 | length 139.6
  Top Layer w12.1: J36.1@3104.35,906.51 3123.79,925.95 3230.62,925.95 3230.69,925.88 R177.2@3235.52,925.88 R177.2@3235.77,925.63
NetJ38_2: J38.2 R163.2 U55.10 | length 2987.9
  L10 SIGNAL w4: J38.2@1857.76,1475.36 1857.76,1460.6 1888.26,1430.1 1888.26,1343.28 1911.1,1320.43 2189.86,1320.43 2213.43,1344.01 2213.43,1419.02 2224.9,1430.49 2378.39,1430.49 2404.9,1456.99 2582.53,1456.99 2655.66,1383.87 3027.57,1383.87 3041.88,1398.18 3041.88,1421.37 3047.5,1426.99 3253.07,1426.99 3306.78,1373.28 3420.51,1373.28 3456.71,1409.47 3572.52,1409.47 3621.32,1458.27 3655.89,1458.27 3690.84,1493.23 3691.55,1493.23 3700.06,1501.73 3736.06,1501.73 3744.57,1493.23 4194.95,1493.23 4224.01,1522.29 4256.37,1522.29 4277.82,1543.74 4350.85,1543.74 4367.48,1527.12 v1(4367.48,1508.76)
  Bottom Layer w8: U55.10@4360.39,1508.74 v1(4367.48,1508.76)
  Bottom Layer w12: J38.2@1857.76,1475.36 R163.2@1857.76,1535.36
NetJ39_1: J39.1 R210.1 U53.2 | length 611.3
  Bottom Layer w5: U53.2@2882.43,2270.28 2883.46,2271.3 2901.76,2271.3 2919.16,2288.7 2919.16,2300.27 2919.16,2303.98 R210.1@2922.96,2307.78 2966.34,2307.78 ; 3018.59,2360.04 2966.34,2307.78 ; J39.1@3275.43,2597.26 3246.65,2568.47 3227.03,2568.47 2966.34,2307.78
NetJ40_1: J40.1 R165.1 U56.10 | length 3634.9
  Bottom Layer w5: J40.1@1857.76,1625.36 1921.89,1561.23 1976.38,1561.23 2007.27,1530.35 2007.27,1292.17 2190.61,1108.82 2190.61,759.45 2324.65,625.41 2339.25,625.41 2345.66,619 2715,619 2725.64,608.36 2725.64,556.97 2769.22,513.39 2955.37,513.39 2977,535.02 4017.62,535.02 4128.82,646.22 4234.99,646.22 4384.55,795.78 4420.91,795.78 4454.14,762.55 v1(4454.14,760.91)
  Bottom Layer w8: R165.1@1797.76,1625.36 J40.1@1857.76,1625.36 ; U56.10@4446.14,752.91 v1(4454.14,760.91)
NetJ45_1: J45.1 R215.1 U61.10 | length 1577.7
  Bottom Layer w5: U61.10@1780.22,2213.57 1780.22,2214.46 1781.65,2215.89 v1(1786.39,2215.89) 1809.26,2215.89 1921.18,2327.81 2075.84,2327.81 2336.62,2067.04 2336.62,1815.15 2449.26,1702.51 2449.26,1466.87 J45.1@2357.76,1375.36 2372.22,1360.9 R215.1@2372.22,1292.17
NetPP4_1: PP4.1 R40.1 U2.6 | length 156.3
  Bottom Layer w7: U2.6@4267.42,2412.87 R40.1@4302.42,2412.87 4304.56,2415.02 4304.56,2424.96 4352.42,2472.81 PP4.1@4352.42,2513.5
NetR1_2: R1.2 R2.1 R3.2 | length 61.3
  Top Layer w12.1: R1.2@4849.4,880.25 R3.2@4849.4,903.25 4849.4,909.18 cw(c4860.51,909.18) 4849.82,912.21 cw(c4860.51,909.18) 4860.51,920.28 ccw(c4860.51,927.29) 4867.51,927.29 R2.1@4867.51,931.25
NetR5_1: R5.1 R6.2 R7.1 | length 61.3
  Top Layer w12.1: R7.1@4889.53,931.25 4889.53,927.29 ccw(c4896.53,927.29) 4896.53,920.28 cw(c4896.53,909.18) 4907.22,912.21 cw(c4896.53,909.18) 4907.64,909.18 R5.1@4907.64,903.25 R6.2@4907.64,880.25
NetR8_2: R8.2 R9.1 R10.2 | length 61.3
  Top Layer w12.1: R8.2@4321.98,962.41 4350.91,962.41 cw(c4350.91,951.3) 4353.94,961.99 cw(c4350.91,951.3) 4362.02,951.3 ccw(c4369.02,951.3) 4369.02,944.3 R9.1@4372.98,944.3
NetR12_1: R12.1 R13.2 R14.1 | length 61.3
  Top Layer w12.1: R13.2@4321.98,904.17 4350.91,904.17 ccw(c4350.91,915.28) 4353.94,904.59 ccw(c4350.91,915.28) 4362.02,915.28 cw(c4369.02,915.28) 4369.02,922.28 R14.1@4372.98,922.28
NetR15_2: R15.2 R16.1 R18.2 | length 46
  Bottom Layer w12.1: R16.1@2955,1356.43 R15.2@2955,1402.43
NetR19_2: R19.2 R20.1 R21.2 | length 61.3
  Top Layer w12.1: R20.1@4889.56,1785.28 4889.56,1789.25 cw(c4896.56,1789.25) 4896.56,1796.25 ccw(c4896.56,1807.36) 4907.24,1804.32 ccw(c4896.56,1807.36) 4907.67,1807.36 R21.2@4907.67,1813.28 R19.2@4907.67,1836.28
NetR23_1: R23.1 R24.2 R25.1 | length 61.3
  Top Layer w12.1: R24.2@4849.42,1836.28 R23.1@4849.42,1813.28 4849.42,1807.36 ccw(c4860.53,1807.36) 4849.85,1804.32 ccw(c4860.53,1807.36) 4860.53,1796.25 cw(c4860.53,1789.25) 4867.53,1789.25 R25.1@4867.53,1785.28
NetR26_2: R26.2 R27.1 R28.2 | length 61.3
  Top Layer w12.1: R26.2@4321.98,1812.39 R28.2@4344.98,1812.39 4350.91,1812.39 cw(c4350.91,1801.28) 4353.94,1811.97 cw(c4350.91,1801.28) 4362.02,1801.28 ccw(c4369.02,1801.28) 4369.02,1794.28 R27.1@4372.98,1794.28
NetR30_1: R30.1 R31.2 R32.1 | length 61.3
  Top Layer w12.1: R31.2@4321.98,1754.15 R30.1@4344.98,1754.15 4350.91,1754.15 ccw(c4350.91,1765.25) 4353.94,1754.57 ccw(c4350.91,1765.25) 4362.02,1765.25 cw(c4369.02,1765.25) 4369.02,1772.26 R32.1@4372.98,1772.26
NetR34_1: R34.1 R54.1 U2.15 | length 54.8
  Bottom Layer w7.4: U2.15@4267.42,2235.71 4290.48,2235.71 4290.91,2235.27 4294.82,2235.27 4297.42,2232.68 R34.1@4297.42,2231.89
  Bottom Layer w12.1: R34.1@4297.66,2232.19 R54.1@4320.42,2232.19
NetR34_2: R34.2 R55.1 U2.16 | length 55.8
  Bottom Layer w7.4: U2.16@4267.42,2216.02 4290.48,2216.02 4293.28,2213.23 4294.82,2213.23 4297.42,2210.63 R34.2@4297.42,2209.84
  Bottom Layer w12.1: R34.2@4297.66,2209.54 R55.1@4320.42,2209.54
NetR35_1: R35.1 R58.1 U2.13 | length 55.8
  Bottom Layer w7.4: U2.13@4267.42,2275.08 4290.48,2275.08 4293.28,2277.87 4294.82,2277.87 4297.42,2280.47 R35.1@4297.42,2281.26
  Bottom Layer w12.1: R35.1@4297.66,2281.56 R58.1@4320.42,2281.56
NetR35_2: R35.2 R61.1 U2.14 | length 54.8
  Bottom Layer w7.4: U2.14@4267.42,2255.39 4290.48,2255.39 4290.91,2255.82 4294.82,2255.82 4297.42,2258.42 R35.2@4297.42,2259.21
  Bottom Layer w12.1: R35.2@4297.66,2258.91 R61.1@4320.42,2258.91
NetR36_1: R36.1 R62.1 U2.24 | length 59.2
  Bottom Layer w7.4: R36.1@4090.53,2160.43 4090.58,2160.43 4091.31,2160.43 4093.91,2163.03 4093.91,2163.82 4104.03,2173.94 U2.24@4104.03,2190.43
  Bottom Layer w12.1: R36.1@4090.58,2160.43 4090.83,2160.18 R62.1@4090.83,2137.43
NetR36_2: R36.2 R63.1 U2.25 | length 60.6
  Bottom Layer w7.4: R36.2@4068.18,2160.18 4069.02,2160.18 4071.87,2163.03 4071.87,2163.87 4075.74,2167.74 4075.74,2169.92 4083.12,2177.3 4083.12,2189.21 U2.25@4084.34,2190.43
  Bottom Layer w12.1: R63.1@4068.18,2137.43 4068.18,2160.18 4068.43,2160.43 R36.2@4068.48,2160.43
NetR38_1: R38.1 R80.1 U2.51 | length 54.8
  Bottom Layer w7.4: U2.51@3985.92,2535.89 3985.92,2558.95 3986.35,2559.39 3986.35,2563.29 3988.95,2565.89 R38.1@3989.74,2565.89
  Bottom Layer w12.1: R38.1@3989.44,2566.14 R80.1@3989.44,2588.89
NetR38_2: R38.2 R81.1 U2.52 | length 56.2
  Bottom Layer w7.4: U2.52@4005.6,2536.89 4005.6,2559.95 4008.4,2562.75 4008.4,2564.29 R38.2@4011,2566.89
  Bottom Layer w12.1: R38.2@4011,2566.89 R38.2@4011.79,2566.89 R38.2@4011.79,2566.89 4012.09,2567.14 R81.1@4012.09,2589.89
NetR39_1: R39.1 R166.1 U2.49 | length 55.8
  Bottom Layer w7.4: R39.1@3940.37,2566.89 3941.16,2566.89 3943.75,2564.29 3943.75,2562.75 3946.55,2559.95 U2.49@3946.55,2536.89
  Bottom Layer w12.1: R39.1@3940.07,2567.14 R166.1@3940.07,2589.89
NetR39_2: R39.2 R181.1 U2.50 | length 54.8
  Bottom Layer w7.4: R39.2@3962.42,2566.89 3963.2,2566.89 3965.8,2564.29 3965.8,2560.39 3966.23,2559.95 U2.50@3966.23,2536.89
  Bottom Layer w12.1: R39.2@3962.72,2567.14 R181.1@3962.72,2589.89
NetR45_1: R45.1 U3.4 U4.4 | length 52.7
  Bottom Layer w12: U3.4@2342.36,855.57 2342.43,855.5 2375.1,855.5 2375.17,855.57 U4.4@2375.16,875.43
NetR46_2: R46.2 R219.2 U4.1 | length 2220.9
  L16 PWR/SIG w5: v1(1807.08,2134.67) 1781.64,2109.23 1535.37,2109.23 1528.88,2102.73 1467.8,2102.73 1462.82,2107.71 1430.54,2107.71 1414.5,2091.67 1414.5,2008 1447.14,1975.36 1669.18,1975.36 1911.44,1733.1 1911.44,1346.67 2007.64,1250.47 2089.53,1250.47 v1(2390,950)
  Bottom Layer w5: v1(1807.08,2134.67) 1807.08,2136.83 1814.87,2144.62 R219.2@1814.87,2155.21 ; v1(2390,950) 2390,948.48 2398.79,939.7 U4.1@2398.79,914.8 R46.2@2418.79,914.8
NetR49_1: R49.1 U3.1 | length 40
  Bottom Layer w5: R49.1@2240,740.77 U3.1@2240,780.77
NetR52_2: R52.2 R60.1 R64.2 U7.10 | length 1263.3
  Bottom Layer w5: v1(1096.23,1956.38) 1099.1,1953.51 1106.52,1953.51 1115.15,1944.88 1320.26,1944.88 1400.59,1864.54 1448.13,1864.54 1550.83,1967.25 1762.37,1967.25 1908.98,2113.86 1968.82,2113.86 2002.25,2147.28 2002.25,2250.26 v1(1964.76,2287.75) 1967.63,2290.62 1972,2290.62 1979.17,2297.79 R52.2@1979.96,2297.79
  Bottom Layer w8: v1@1091.23,1964.63 U7.10@1091.23,1991.38
NetR57_2: R57.2 U6.13 | length 29.6
  Bottom Layer w8: R57.2@972.49,2333.5 973.28,2333.5 975.58,2335.8 975.58,2336.59 982.49,2343.5 U6.13@997.49,2343.5
NetR64_1: R64.1 U8.4 | length 30
  Top Layer w8: R64.1@2004.13,2287.75 U8.4@2034.13,2287.75
NetR65_2: R65.2 U7.13 | length 29.6
  Bottom Layer w8: R65.2@1011.12,1989.25 1011.9,1989.25 1014.2,1991.55 1014.2,1992.34 1021.12,1999.25 U7.13@1036.12,1999.25
NetR68_2: R68.2 R70.2 R207.2 | length 80.1
  Bottom Layer w6: R70.2@604.43,2083.35 604.43,2082.56 607.73,2079.27 614.34,2079.27 637,2056.61 642.56,2056.61 645.86,2053.31 R207.2@645.86,2052.52 R68.2@670.87,2052.52
NetR75_2: R75.2 U11.13 | length 29.6
  Bottom Layer w8: R75.2@1544.13,2121.54 1544.92,2121.54 1547.22,2123.83 1547.22,2124.62 1554.13,2131.54 U11.13@1569.13,2131.54
NetR78_1: R78.1 U14.4 | length 53
  Top Layer w6: R78.1@567.36,2026.04 U14.4@567.36,2050.04
  Top Layer w8: v1(556.67,2001.47) 556.67,2002.73 567.36,2013.41 R78.1@567.36,2026.04
NetR78_2: R78.2 R82.2 R185.2 | length 51
  Top Layer w6: R185.2@521.32,1999.04 R82.2@521.32,2026.04 R78.2@545.32,2026.04
NetR79_2: R79.2 SW6.2 | length 64.5
  Bottom Layer w5: SW6.2@2791.03,572.55 2795.76,572.55 2834.68,611.47 R79.2@2839.41,611.47
NetR89_1: R89.1 SW4.2 | length 50
  Bottom Layer w12: R89.1@2666.03,522.55 SW4.2@2666.03,572.55
NetR90_1: R90.1 SW2.2 | length 50
  Bottom Layer w12: R90.1@2416.03,522.55 SW2.2@2416.03,572.55
NetR91_1: R91.1 SW3.2 | length 50
  Bottom Layer w12: R91.1@2541.03,522.55 SW3.2@2541.03,572.55
NetR102_1: R102.1 U26.24 | length 39.1
  Bottom Layer w8: R102.1@1773.07,636.2 1773.07,638.17 1783.07,648.17 U26.24@1783.07,671.2
NetR109_2: R109.2 U29.10 | length 50
  Bottom Layer w9: R109.2@1341.26,286.05 U29.10@1341.26,336.05
NetR113_2: R113.2 R115.1 U36.24 | length 84
  Bottom Layer w7: R115.1@139.09,1920.69 R113.2@139.09,1886.69 U36.24@189.09,1886.69
NetR114_1: R114.1 R117.2 U36.22 | length 467.5
  Top Layer w10: v1(174.09,1847.32) 176.01,1845.41 182.93,1845.41 246.89,1781.45 482.73,1781.45 v1(565.18,1863.9)
  Bottom Layer w10: v1(174.09,1847.32) U36.22@189.09,1847.32
NetR116_2: R116.2 U36.23 | length 57.4
  Bottom Layer w7: R116.2@139.09,1852.01 141.06,1852.01 147.4,1858.35 147.4,1860.32 154.09,1867.01 U36.23@189.09,1867.01
NetR121_1: R121.1 U38.5
  other v1: 209.01,1342.56
NetR122_2: R122.2 R123.2 U37.37 | length 70
  Bottom Layer w10: R123.2@291.84,1309.41 R122.2@321.84,1309.41 U37.37@321.84,1349.41
NetR123_1: R123.1 R124.2 U37.38 | length 138
  Bottom Layer w10: R124.2@287.16,1240.04 ccw(c287.16,1244.72) 291.84,1244.72 R123.1@291.84,1270.04 291.84,1272.01 287,1276.85 285.03,1276.85 267.43,1294.45 267.43,1321.97 U37.38@297.24,1351.77
NetR126_1: R126.1 R127.2 U39.40 | length 70
  Bottom Layer w9: R127.2@248.38,953.07 U39.40@288.38,953.07
  Bottom Layer w10: R127.2@248.38,953.07 R126.1@248.38,983.07
NetR128_2: R128.2 R129.2 U39.37 | length 70
  Bottom Layer w10: R129.2@291.84,859.92 R128.2@321.84,859.92 U39.37@321.84,899.92
NetR129_1: R129.1 R130.2 U39.38 | length 130.7
  Bottom Layer w10: R130.2@291.84,795.23 R129.1@291.84,820.55 291.84,822.52 287,827.36 285.03,827.36 267.43,844.96 267.43,872.48 U39.38@297.23,902.28
NetR131_1: R131.1 U40.4 U65.1 | length 401.2
  Top Layer w8: R131.1@1069.37,1635 v1(1070.35,1635) 1071.34,1635 1077.18,1640.84 1077.18,1642.16 1085.14,1650.12 U40.4@1104.37,1650.12
  L16 PWR/SIG w5: v3(943.67,1442.03) 943.67,1522.62 999.08,1578.03 999.08,1641.04 1017.92,1659.88 1045.48,1659.88 v1(1070.35,1635)
  Bottom Layer w8: U65.1@928.31,1400.62 928.31,1426.66 v3(943.67,1442.03)
NetR132_1: R132.1 U41.5 | length 139.7
  Bottom Layer w10: U41.5@1164.72,1763.86 1164.72,1740.84 1174.25,1731.31 1213.69,1731.31 1244.76,1700.24 1244.76,1687.24 R132.1@1249.61,1682.4
NetR133_1: R133.1 R135.2 U40.5
NetR136_1: R136.1 U42.5 | length 89.7
  Bottom Layer w10: U42.5@1264.72,1763.86 1264.72,1738.05 1284.61,1718.17 R136.1@1284.61,1682.4
NetR137_1: R137.1 U43.4 U65.2 | length 191.6
  Top Layer w8: R137.1@1069.37,1335 v1(1070.35,1335) 1071.34,1335 1077.18,1340.84 1077.18,1342.16 1085.14,1350.12 U43.4@1104.37,1350.12
  Bottom Layer w8: U65.2@953.9,1400.62 953.91,1390.44 969.45,1374.9 978.47,1374.9 996.06,1357.31 1048.04,1357.31 v1(1070.35,1335)
NetR138_1: R138.1 U44.5 | length 139.7
  Bottom Layer w10: U44.5@1164.72,1463.86 1164.72,1440.84 1174.25,1431.31 1213.69,1431.31 1244.76,1400.24 1244.76,1387.24 R138.1@1249.61,1382.4
NetR139_1: R139.1 R141.2 U43.5
NetR142_1: R142.1 U45.5 | length 89.7
  Bottom Layer w10: U45.5@1264.72,1463.86 1264.72,1438.05 1284.61,1418.17 R142.1@1284.61,1382.4
NetR143_1: R143.1 U46.4 U67.1 | length 314.3
  Top Layer w8: R143.1@1069.37,735 v1(1070.35,735) 1071.34,735 1077.18,740.84 1077.18,742.16 1085.14,750.12 U46.4@1104.37,750.12
  Bottom Layer w8: U67.1@1050.63,950.47 1049.4,949.24 1049.4,926.3 1014.13,891.03 1014.13,857.26 1002.37,845.5 1002.37,788.29 1014.09,776.58 1028.78,776.58 v1(1070.35,735)
NetR144_2: R144.2 U47.5 | length 139.7
  Bottom Layer w10: U47.5@1164.72,863.86 1164.72,840.84 1174.25,831.31 1213.69,831.31 1244.76,800.24 1244.76,787.24 R144.2@1249.61,782.4
NetR145_1: R145.1 R147.2 U46.5
NetR148_1: R148.1 U48.5 | length 89.7
  Bottom Layer w10: U48.5@1264.72,863.86 1264.72,838.05 1284.61,818.17 R148.1@1284.61,782.4
NetR149_1: R149.1 U49.4 U67.2 | length 129
  Top Layer w8: R149.1@1069.37,1035 v1(1070.35,1035) 1071.34,1035 1077.18,1040.84 1077.18,1042.16 1085.14,1050.12 U49.4@1104.37,1050.12
  Bottom Layer w8: v1(1070.35,1035) 1070.35,966.18 1076.22,960.32 U67.2@1076.22,950.47
NetR150_2: R150.2 U50.5 | length 139.7
  Bottom Layer w10: U50.5@1164.72,1163.86 1164.72,1140.84 1174.25,1131.31 1213.69,1131.31 1244.76,1100.24 1244.76,1087.24 R150.2@1249.61,1082.4
NetR151_1: R151.1 R153.2 U49.5
NetR154_1: R154.1 U51.5 | length 89.7
  Bottom Layer w10: U51.5@1264.72,1163.86 1264.72,1138.05 1284.61,1118.17 R154.1@1284.61,1082.4
NetR155_1: R155.1 U53.13 | length 30.5
  Bottom Layer w7.4: R155.1@2796.6,2345.55 2797.78,2344.37 U53.13@2797.78,2315.55
NetR155_2: R155.2 U53.14 | length 30.5
  Bottom Layer w7.4: U53.14@2817.47,2315.55 2817.47,2344.37 R155.2@2818.65,2345.55
NetR156_1: R156.1 U54.13 | length 32.4
  Bottom Layer w8: U54.13@5427.96,2307.65 5451.77,2307.65 5453.46,2309.34 5455.66,2309.34 5457.96,2311.63 R156.1@5457.96,2312.42
NetR156_2: R156.2 U54.14 | length 31.1
  Bottom Layer w8: U54.14@5427.96,2287.96 5455.66,2287.96 5457.96,2290.26 R156.2@5457.96,2290.37
NetR161_1: R161.1 U54.15 | length 30.9
  Bottom Layer w8: U54.15@5427.96,2268.27 5455.73,2268.27 R161.1@5457.96,2266.04
NetR161_2: R161.2 U54.16 | length 32.4
  Bottom Layer w8: U54.16@5427.96,2248.58 5451.77,2248.58 5453.28,2247.08 5455.66,2247.08 5457.96,2244.78 R161.2@5457.96,2243.99
NetR178_1: R178.1 U53.9 | length 30.5
  Bottom Layer w7.4: R178.1@2742.2,2229.72 2743.37,2230.9 U53.9@2772.2,2230.9
NetR178_2: R178.2 U53.10 | length 30.5
  Bottom Layer w7.4: R178.2@2742.2,2251.77 2743.37,2250.59 U53.10@2772.2,2250.59
NetR179_1: R179.1 U35.3 | length 178.5
  Bottom Layer w8: U35.3@5447.6,107 5448.36,107.76 5448.36,128.65 5466.08,146.37 R179.1@5597.52,146.37
NetR182_2: R182.2 R201.1 | length 427.1
  Top Layer w5: R201.1@5548.71,1109.09 5548.71,802.48 v1(5568.46,782.72)
  Bottom Layer w5: R182.2@5480.09,792.79 5558.03,792.79 5568.1,782.72 v1(5568.46,782.72)
NetR204_1: R204.1 U55.1 | length 39
  Bottom Layer w7.4: U55.1@4366.29,1485.12 4366.53,1484.88 4381.08,1484.88 4382.51,1483.45 4396.63,1483.45 4401.73,1488.55 R204.1@4402.51,1488.55
NetR205_1: R205.1 U55.2 | length 39
  Bottom Layer w7.4: U55.2@4366.29,1469.37 4366.53,1469.61 4381.08,1469.61 4382.51,1471.05 4396.63,1471.05 4401.73,1465.95 R205.1@4402.51,1465.95
NetR206_1: R206.1 U64.4 | length 40
  Bottom Layer w8: U64.4@169.01,1551.77 R206.1@209.01,1551.77
NetR206_2: R206.2 R227.2 R228.2 U37.1 U37.46 | length 205.8
  Bottom Layer w10: R228.2@149.09,1615.76 R227.2@149.09,1585.76 237.62,1585.76 248.38,1575 R206.2@248.38,1551.77 U37.1@297.24,1551.77
NetR207_1: R207.1 U12.4 | length 39
  Top Layer w8: v1(627.05,2030.04) U12.4@627.05,2050.04
  Bottom Layer w8: v1(627.05,2030.04) 627.26,2030.26 645.65,2030.26 R207.1@645.86,2030.47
